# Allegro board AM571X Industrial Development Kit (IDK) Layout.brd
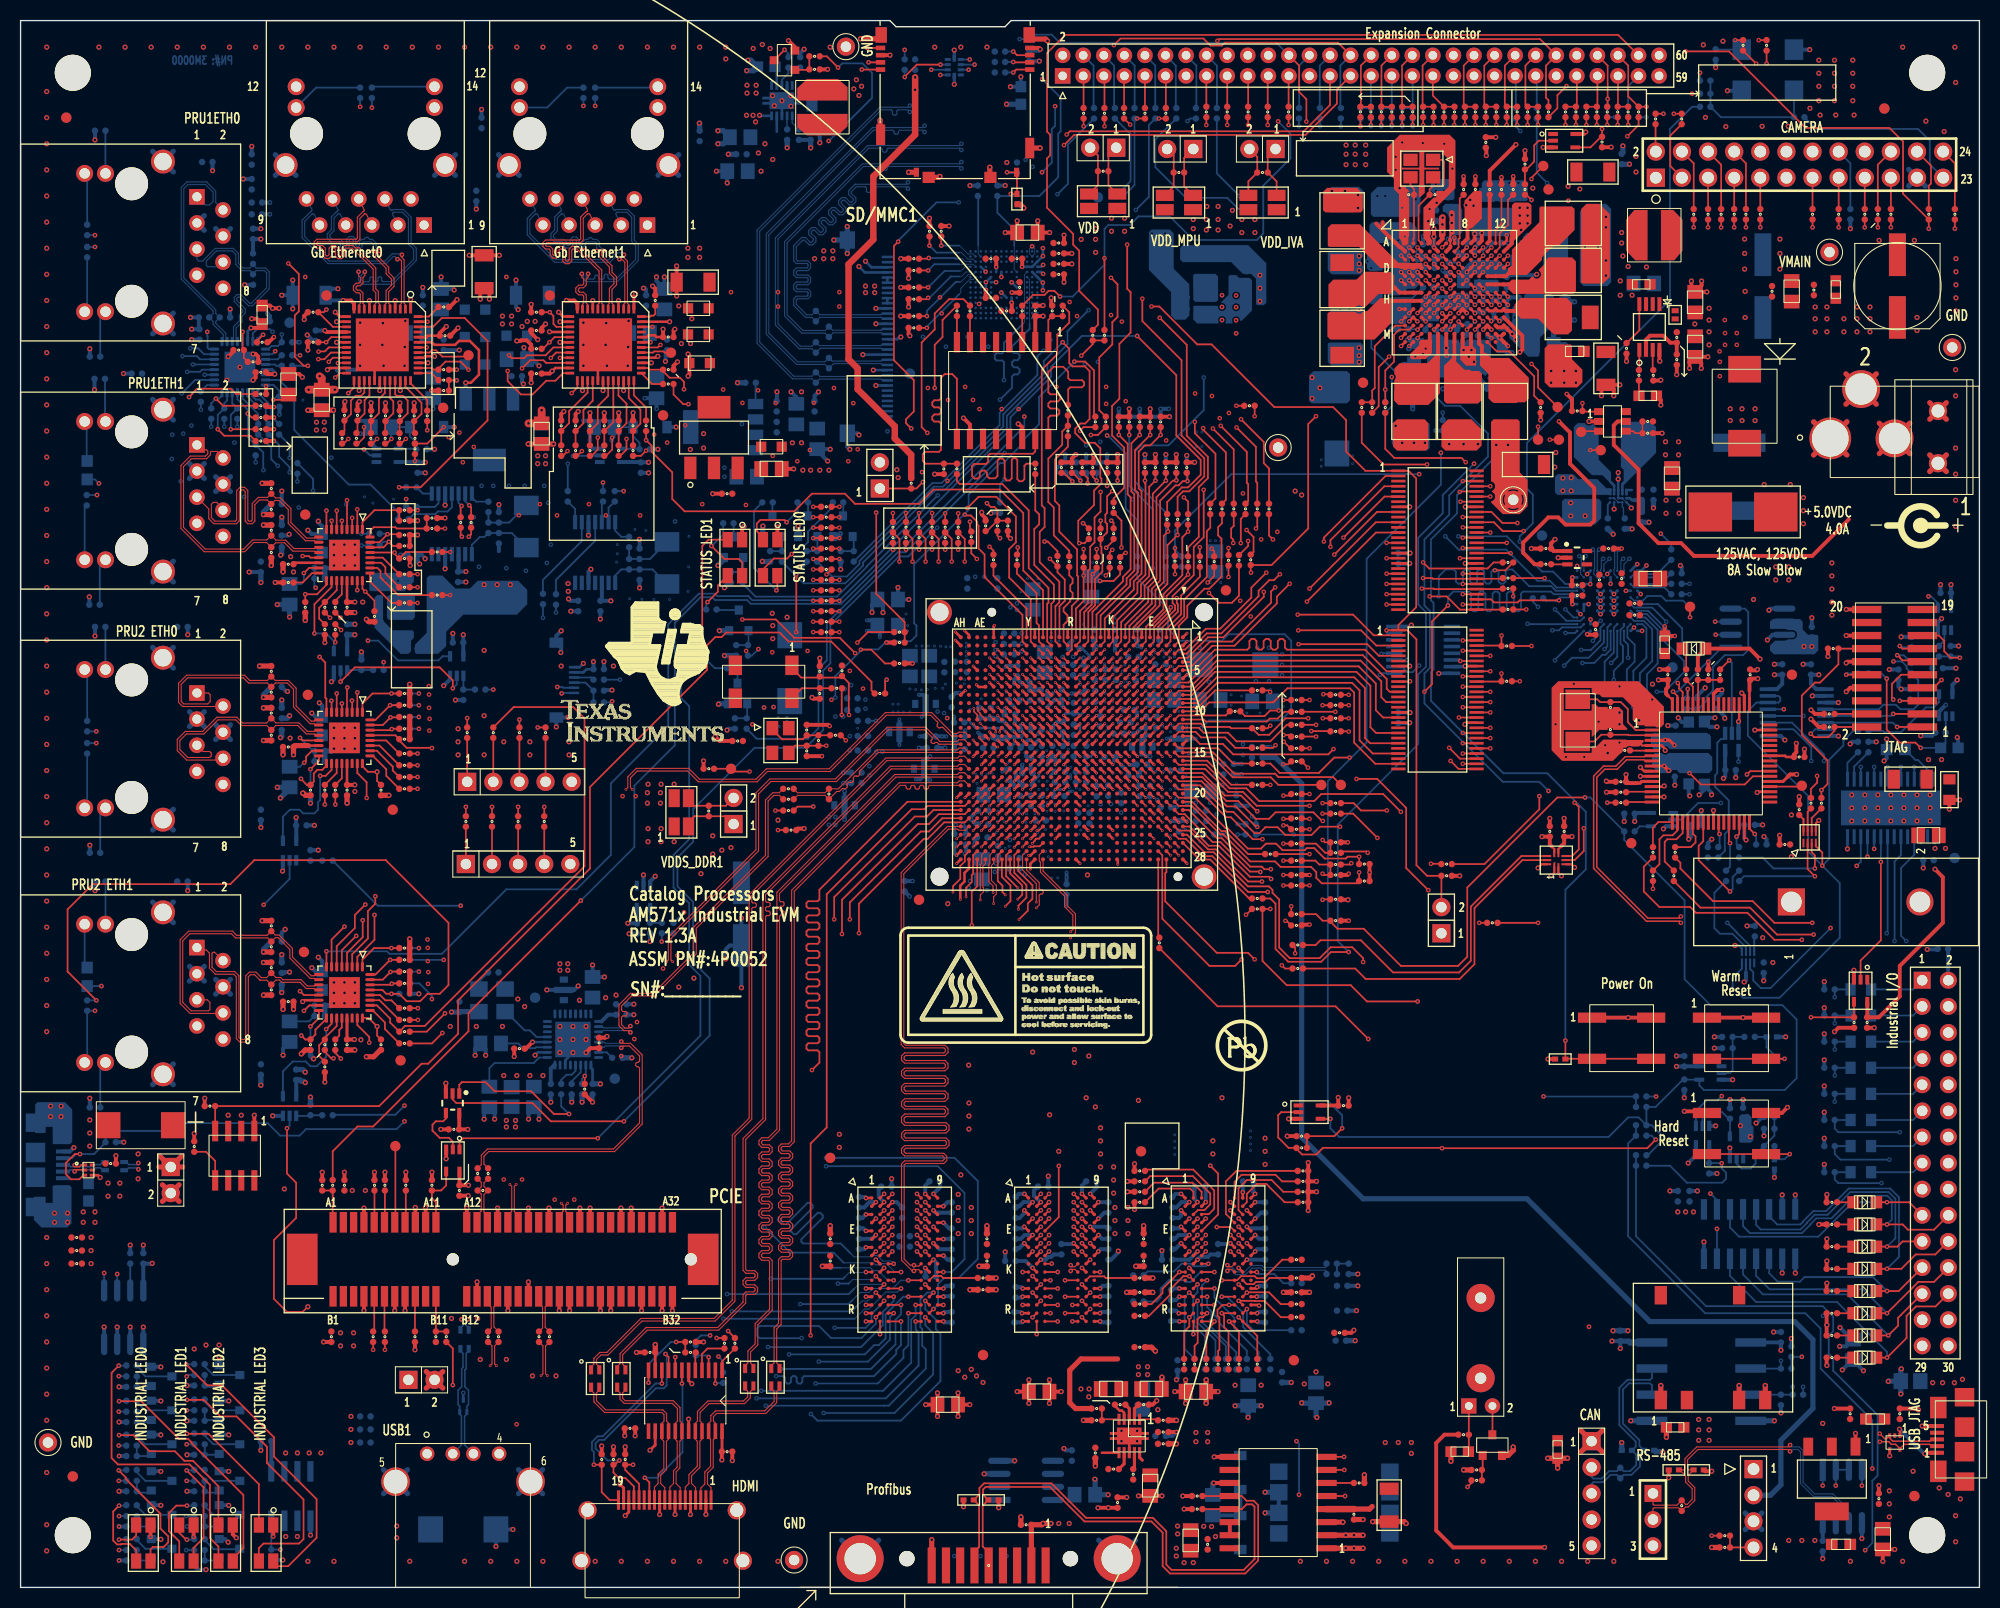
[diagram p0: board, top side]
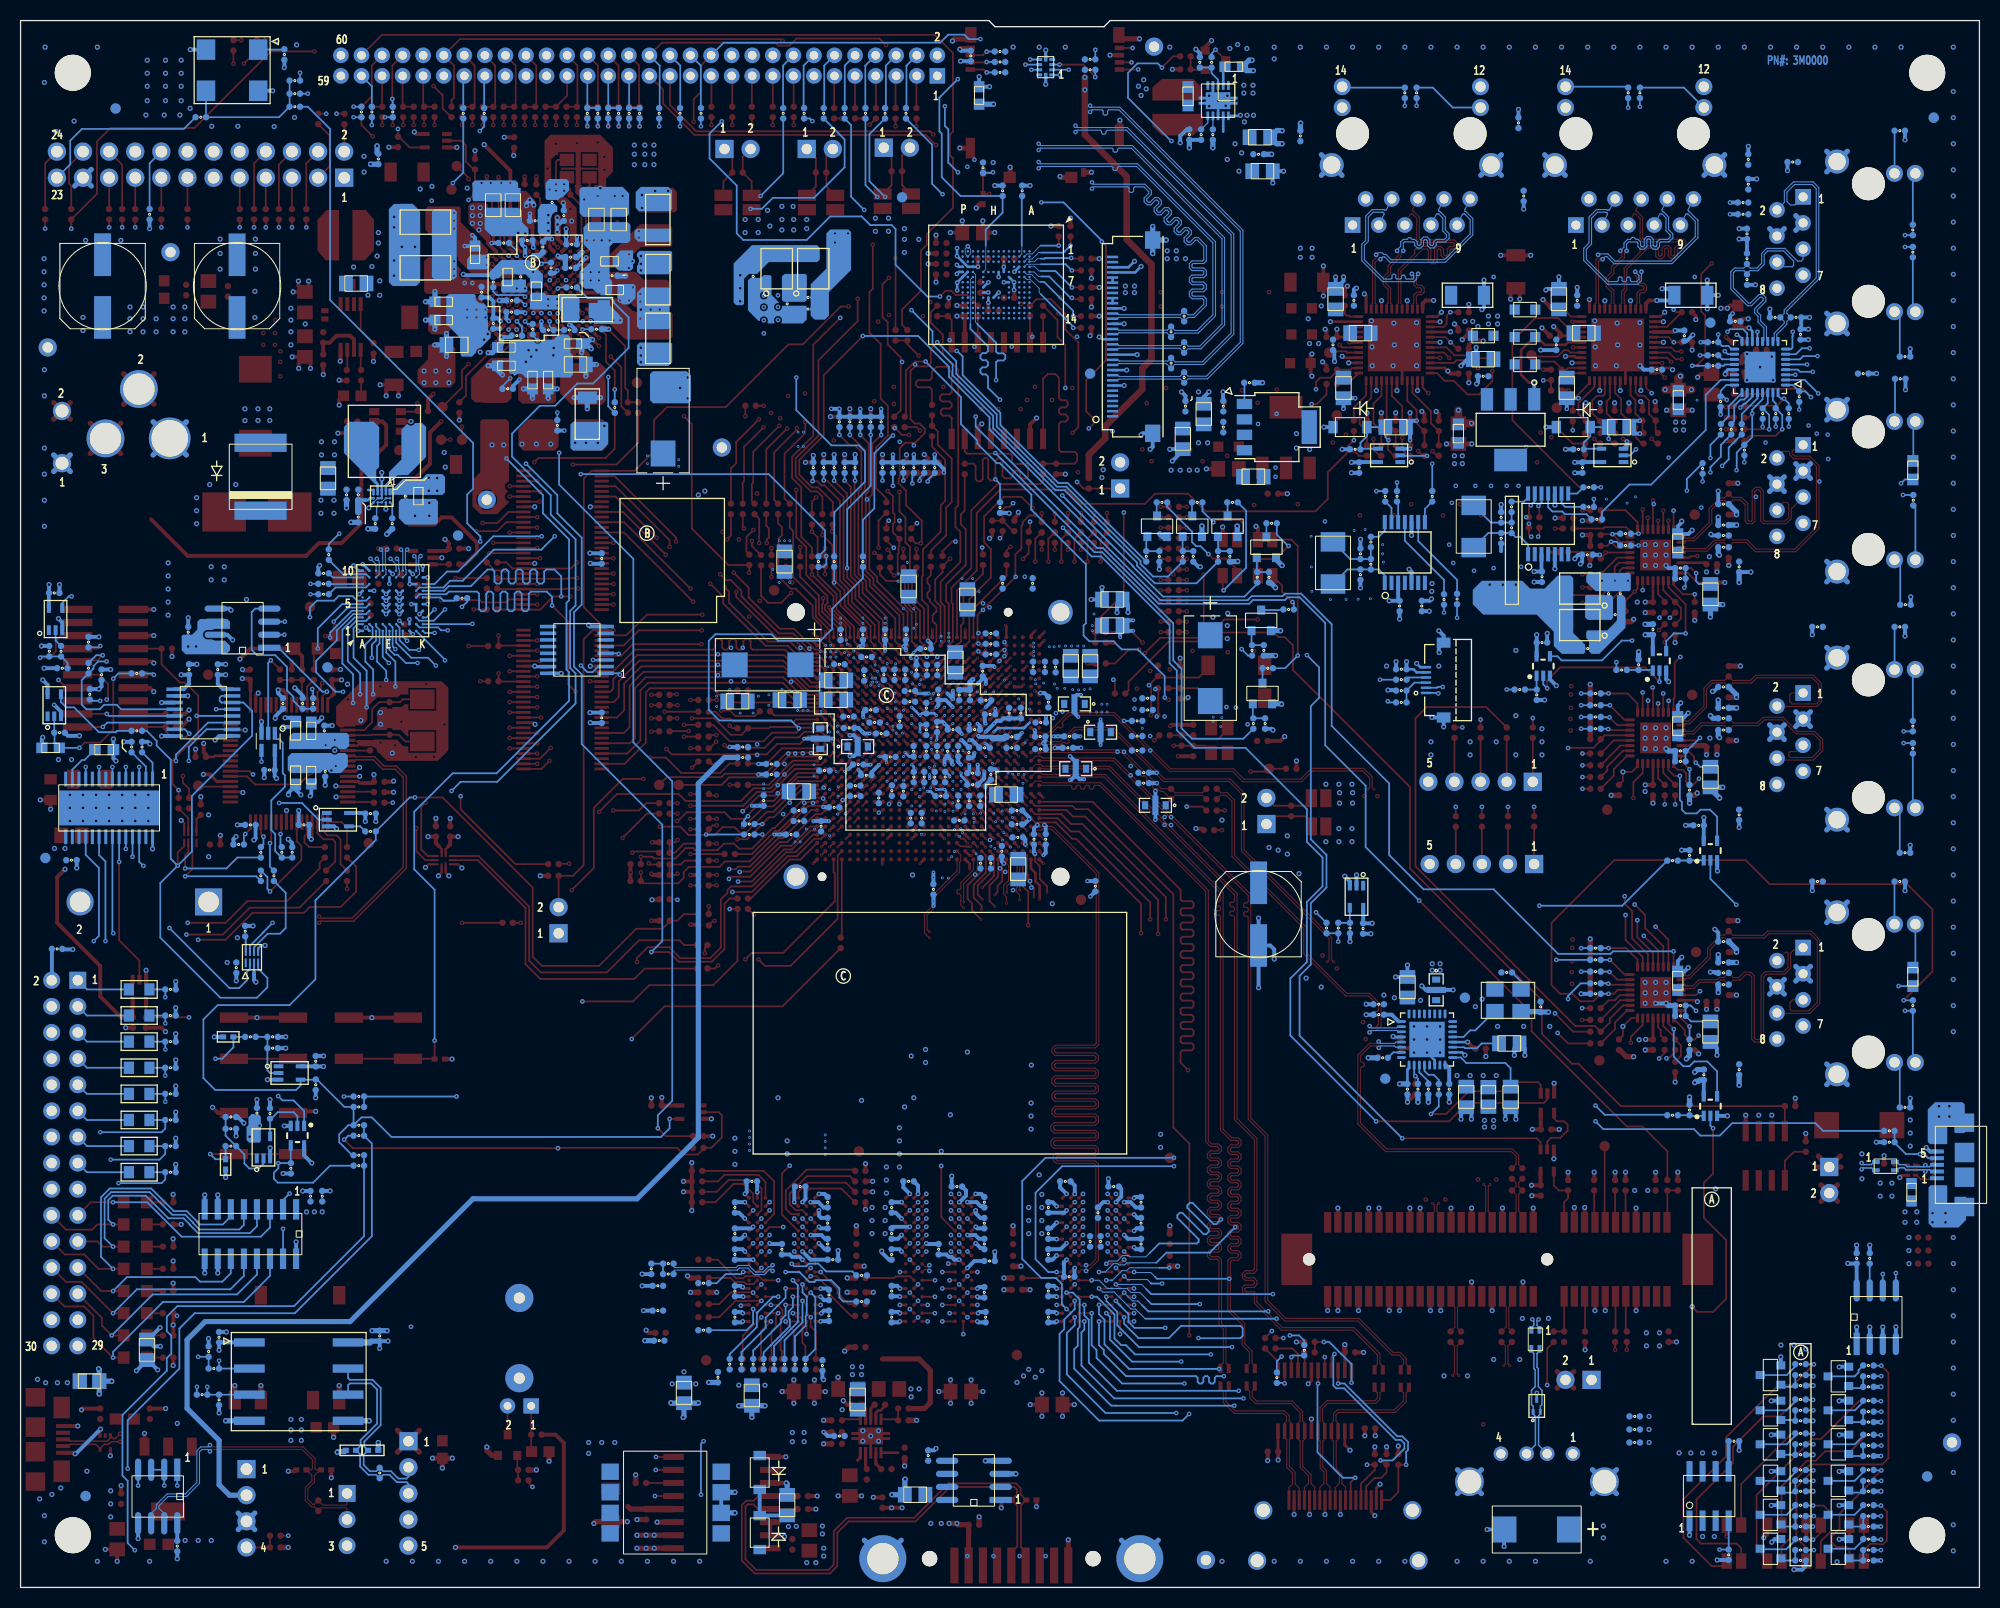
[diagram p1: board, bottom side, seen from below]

Outline 190.5 x 152.4 mm; copper layers: TOP, L2_GND1, L3_SIG1, L4_SIG2, L5_GND2, L6_PWR1, L7_PWR2, L8_GND3, L9_SIG3, L10_SIG4, L11_GND4, BOTTOM. Coordinates in mm from the lower left corner of the outline.
Outline path: 0,152.4 0,0 190.5,0 190.5,152.4 96.34,152.4 95.74,151.8 85.14,151.8 84.54,152.4 0,152.4

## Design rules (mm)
net group AM57XX_HDMI_CLK+: nets AM57XX_HDMI_CLK+ HDMI_CLK+
net group AM57XX_HDMI_CLK-: nets AM57XX_HDMI_CLK- HDMI_CLK-
net group AM57XX_HDMI_TX0+: nets AM57XX_HDMI_TX0+ HDMI_TX0+
net group AM57XX_HDMI_TX0-: nets AM57XX_HDMI_TX0- HDMI_TX0-
net group AM57XX_HDMI_TX1+: nets AM57XX_HDMI_TX1+ HDMI_TX1+
net group AM57XX_HDMI_TX1-: nets AM57XX_HDMI_TX1- HDMI_TX1-
net group AM57XX_HDMI_TX2+: nets AM57XX_HDMI_TX2+ HDMI_TX2+
net group AM57XX_HDMI_TX2-: nets AM57XX_HDMI_TX2- HDMI_TX2-
net group AM57XX_PCIE_PETN0: nets AM57XX_PCIE_PETN0 PCIECONN_PETN0
net group AM57XX_PCIE_PETN1: nets AM57XX_PCIE_PETN1 PCIECONN_PETN1
net group AM57XX_PCIE_PETP0: nets AM57XX_PCIE_PETP0 PCIECONN_PETP0
net group AM57XX_PCIE_PETP1: nets AM57XX_PCIE_PETP1 PCIECONN_PETP1
net group AM57XX_PCIE_REF_CLKN: nets AM57XX_PCIE_REF_CLKN SERDES_REF_CLKN
net group AM57XX_PCIE_REF_CLKP: nets AM57XX_PCIE_REF_CLKP SERDES_REF_CLKP
net group AM57XX_PRU1ETH1_TXCLK: nets AM57XX_PRU1ETH1_TXCLK PRU1ETH1_TXCLK
net group AM57XX_PRU1ETH1_TXD2: nets AM57XX_PRU1ETH1_TXD2 PRU1ETH1_TXD2
net group AM57XX_PRU1ETH1_TXD3: nets AM57XX_PRU1ETH1_TXD3 PRU1ETH1_TXD3
net group AM57XX_PRU1ETH1_TXEN: nets AM57XX_PRU1ETH1_TXEN PRU1ETH1_TXEN
net group AM57XX_PRU2ETH0_CRS: nets AM57XX_PRU2ETH0_CRS PRU2ETH0_CRS
net group AM57XX_PRU2ETH0_MRCLK: nets AM57XX_PRU2ETH0_MRCLK PRU2ETH0_RXCLK
net group AM57XX_PRU2ETH0_RXD0: nets AM57XX_PRU2ETH0_RXD0 PRU2ETH0_RXD0
net group AM57XX_PRU2ETH0_RXD1: nets AM57XX_PRU2ETH0_RXD1 PRU2ETH0_RXD1
net group AM57XX_PRU2ETH0_RXD2: nets AM57XX_PRU2ETH0_RXD2 PRU2ETH0_RXD2
net group AM57XX_PRU2ETH0_RXD3: nets AM57XX_PRU2ETH0_RXD3 PRU2ETH0_RXD3
net group AM57XX_PRU2ETH0_RXDV: nets AM57XX_PRU2ETH0_RXDV PRU2ETH0_RXDV
net group AM57XX_PRU2ETH0_RXER: nets AM57XX_PRU2ETH0_RXER PRU2ETH0_RXERR
net group AM57XX_PRU2ETH0_TXCLK: nets AM57XX_PRU2ETH0_TXCLK PRU2ETH0_TXCLK
net group AM57XX_PRU2ETH0_TXD0: nets AM57XX_PRU2ETH0_TXD0 PRU2ETH0_TXD0
net group AM57XX_PRU2ETH0_TXD1: nets AM57XX_PRU2ETH0_TXD1 PRU2ETH0_TXD1
net group AM57XX_PRU2ETH0_TXD2: nets AM57XX_PRU2ETH0_TXD2 PRU2ETH0_TXD2
net group AM57XX_PRU2ETH0_TXD3: nets AM57XX_PRU2ETH0_TXD3 PRU2ETH0_TXD3
net group AM57XX_PRU2ETH0_TXEN: nets AM57XX_PRU2ETH0_TXEN PRU2ETH0_TXEN
net group AM57XX_PRU2ETH1_COL: nets AM57XX_PRU2ETH1_COL PRU2ETH1_COL
net group AM57XX_PRU2ETH1_CRS: nets AM57XX_PRU2ETH1_CRS PRU2ETH1_CRS
net group AM57XX_PRU2ETH1_MRCLK: nets AM57XX_PRU2ETH1_MRCLK PRU2ETH1_RXCLK
net group AM57XX_PRU2ETH1_RXD0: nets AM57XX_PRU2ETH1_RXD0 PRU2ETH1_RXD0
net group AM57XX_PRU2ETH1_RXD1: nets AM57XX_PRU2ETH1_RXD1 PRU2ETH1_RXD1
net group AM57XX_PRU2ETH1_RXD2: nets AM57XX_PRU2ETH1_RXD2 PRU2ETH1_RXD2
net group AM57XX_PRU2ETH1_RXD3: nets AM57XX_PRU2ETH1_RXD3 PRU2ETH1_RXD3
net group AM57XX_PRU2ETH1_RXDV: nets AM57XX_PRU2ETH1_RXDV PRU2ETH1_RXDV
net group AM57XX_PRU2ETH1_RXER: nets AM57XX_PRU2ETH1_RXER PRU2ETH1_RXERR
net group AM57XX_PRU2ETH1_TXCLK: nets AM57XX_PRU2ETH1_TXCLK PRU2ETH1_TXCLK
net group AM57XX_PRU2ETH1_TXD0: nets AM57XX_PRU2ETH1_TXD0 PRU2ETH1_TXD0
net group AM57XX_PRU2ETH1_TXD1: nets AM57XX_PRU2ETH1_TXD1 PRU2ETH1_TXD1
net group AM57XX_PRU2ETH1_TXD2: nets AM57XX_PRU2ETH1_TXD2 PRU2ETH1_TXD2
net group AM57XX_PRU2ETH1_TXD3: nets AM57XX_PRU2ETH1_TXD3 PRU2ETH1_TXD3
net group AM57XX_PRU2ETH1_TXEN: nets AM57XX_PRU2ETH1_TXEN PRU2ETH1_TXEN
net group AM57XX_RGMII1_RD0: nets AM57XX_RGMII1_RD0 ETH1_RXD0
net group AM57XX_RGMII1_RD1: nets AM57XX_RGMII1_RD1 ETH1_RXD1
net group AM57XX_RGMII1_RD2: nets AM57XX_RGMII1_RD2 ETH1_RXD2
net group AM57XX_RGMII1_RD3: nets AM57XX_RGMII1_RD3 ETH1_RXD3
net group AM57XX_RGMII1_RXCLK: nets AM57XX_RGMII1_RXCLK ETH1_RXCLK
net group AM57XX_RGMII1_RXCTL: nets AM57XX_RGMII1_RXCTL ETH1_RXDV
net group AM57XX_RGMII1_TD0: nets AM57XX_RGMII1_TD0 ETH1_TXD0
net group AM57XX_RGMII1_TD1: nets AM57XX_RGMII1_TD1 ETH1_TXD1
net group AM57XX_RGMII1_TD2: nets AM57XX_RGMII1_TD2 ETH1_TXD2
net group AM57XX_RGMII1_TD3: nets AM57XX_RGMII1_TD3 ETH1_TXD3
net group AM57XX_RGMII1_TXCLK: nets AM57XX_RGMII1_TXCLK ETH1_TXCLK
net group AM57XX_RGMII1_TXCTL: nets AM57XX_RGMII1_TXCTL ETH1_TXEN
net group AM57XX_RTCK: nets AM57XX_RTCK RTCK
net group AM57XX_VIN1B_DATA0: nets AM57XX_VIN1B_DATA0 CAM1_DATA0
net group AM57XX_VIN1B_DATA1: nets AM57XX_VIN1B_DATA1 CAM1_DATA1
net group AM57XX_VIN1B_DATA2: nets AM57XX_VIN1B_DATA2 CAM1_DATA2
net group AM57XX_VIN1B_DATA3: nets AM57XX_VIN1B_DATA3 CAM1_DATA3
net group AM57XX_VIN1B_DATA4: nets AM57XX_VIN1B_DATA4 CAM1_DATA4
net group AM57XX_VIN1B_DATA5: nets AM57XX_VIN1B_DATA5 CAM1_DATA5
net group AM57XX_VIN1B_DATA6: nets AM57XX_VIN1B_DATA6 CAM1_DATA6
net group AM57XX_VIN1B_DATA7: nets AM57XX_VIN1B_DATA7 CAM1_DATA7
net group AM57XX_VIN1B_HSYNC: nets AM57XX_VIN1B_HSYNC CAM1_HSYNC
net group AM57XX_VIN1B_PCLK: nets AM57XX_VIN1B_PCLK CAM1_PCLK
net group AM57XX_VIN1B_VSYNC: nets AM57XX_VIN1B_VSYNC CAM1_VSYNC
net group AM571X_RGMII0_RD0: nets AM571X_RGMII0_RD0 ETH0_RXD0
net group AM571X_RGMII0_RD1: nets AM571X_RGMII0_RD1 ETH0_RXD1
net group AM571X_RGMII0_RD2: nets AM571X_RGMII0_RD2 ETH0_RXD2
net group AM571X_RGMII0_RD3: nets AM571X_RGMII0_RD3 ETH0_RXD3
net group AM571X_RGMII0_RXCLK: nets AM571X_RGMII0_RXCLK ETH0_RXCLK
net group AM571X_RGMII0_RXCTL: nets AM571X_RGMII0_RXCTL ETH0_RXDV
net group AM571X_RGMII0_TD0: nets AM571X_RGMII0_TD0 ETH0_TXD0
net group AM571X_RGMII0_TD1: nets AM571X_RGMII0_TD1 ETH0_TXD1
net group AM571X_RGMII0_TD2: nets AM571X_RGMII0_TD2 ETH0_TXD2
net group AM571X_RGMII0_TD3: nets AM571X_RGMII0_TD3 ETH0_TXD3
net group AM571X_RGMII0_TXCLK: nets AM571X_RGMII0_TXCLK ETH0_TXCLK
net group AM571X_RGMII0_TXCTL: nets AM571X_RGMII0_TXCTL ETH0_TXEN
net group AM572X_QSPI_D1: nets AM572X_QSPI_D1 SPIMEM_D1
net group AM572X_USB2_D: nets AM572X_USB2_DM AM572X_USB2_DP
net group JTAG_TCK: nets JTAG_TCK TCK
net group PCIE: nets AM57XX_PCIE_PERN1 AM57XX_PCIE_PERP1
net group PCIE_REFCLKN: nets PCI_CONN_REFN PCIE_REFCLKN
net group PCIE_REFCLKP: nets PCI_CONN_REFP PCIE_REFCLKP
net group PR1_MII1_MR1_CLK: nets PR1_MII1_MR1_CLK PRU1ETH1_RXCLK
net group PR1_MII1_RXD0: nets PR1_MII1_RXD0 PRU1ETH1_RXD0
net group PR1_MII1_RXD1: nets PR1_MII1_RXD1 PRU1ETH1_RXD1
net group PR1_MII1_RXD2: nets PR1_MII1_RXD2 PRU1ETH1_RXD2
net group PR1_MII1_RXD3: nets PR1_MII1_RXD3 PRU1ETH1_RXD3
net group PR1_MII1_RXDV: nets PR1_MII1_RXDV PRU1ETH1_RXDV
net group PR1_MII1_RXER: nets PR1_MII1_RXER PRU1ETH1_RXERR
net group PRU1ETH1_TXD0: nets AM571X_PRU1ETH1_TXD0 PRU1ETH1_TXD0
net group PRU1ETH1_TXD1: nets AM571X_PRU1ETH1_TXD1 PRU1ETH1_TXD1
net group SPIMEM_CSN: nets AM572X_QSPI_CSN SPIMEM_CSN
net group SPIMEM_D0: nets AM572X_QSPI_D0 SPIMEM_D0
net group SPIMEM_D2: nets AM572X_QSPI_D2 SPIMEM_D2
net group SPIMEM_D3: nets AM572X_QSPI_D3 SPIMEM_D3
net group USB2_CONN_D: nets USB2_CONN_DM USB2_CONN_DP
net group AM57XX_MMC1_CLK: nets MMC_CLK
net group AM57XX_MMC1_CMD: nets MMC_CMD
net group AM57XX_MMC1_DAT0: nets MMC_D0
net group AM57XX_MMC1_DAT1: nets MMC_D1
net group AM57XX_MMC1_DAT2: nets MMC_D2
net group AM57XX_MMC1_DAT3: nets MMC_D3
net group AM57XX_PRU1ETH_MDCLK: nets AM57XX_PRU1ETH_MDCLK PRU1ETH0_MDC PRU1ETH1_MDC
net group AM57XX_PRU1ETH_MDDATA: nets AM57XX_PRU1ETH_MDDATA PRU1ETH0_MDIO PRU1ETH1_MDIO
net group AM57XX_PRU2ETH_MDCLK: nets AM57XX_PRU2ETH_MDCLK PRU2ETH0_MDC PRU2ETH1_MDC
net group AM57XX_PRU2ETH_MDDATA: nets AM57XX_PRU2ETH_MDDATA PRU2ETH0_MDIO PRU2ETH1_MDIO
net group CLK: nets AM57XX_CLKOUT3 AM57XX_OSC0_IN AM57XX_OSC0_OUT ETH0GB_25MHZCLK ETH1GB_25MHZCLK INDUS_INPUTCLK N17745755 OSC0_OUT PRU1ETH0_25MHZCLK PRU1ETH1_25MHZCLK PRU2ETH0_25MHZCLK PRU2ETH1_25MHZCLK SRCCLK XTIN XTOUT
net group DDR_ADD: nets DDR_CKE
net group PRU1ETH0: nets PR1_MII0_RXD0 PR1_MII0_RXD1 PR1_MII0_RXD2 PR1_MII0_RXD3 PR1_MII0_RXDV PR1_MII0_RXER PR1_MII0_TXD0 PR1_MII0_TXD1 PR1_MII0_TXD2 PR1_MII0_TXD3 PR1_MII0_TXEN PR1_MII_MR0_CLK PR1_MII_MT0_CLK PRU1ETH0_RXCLK PRU1ETH0_RXD0 PRU1ETH0_RXD1 PRU1ETH0_RXD2 PRU1ETH0_RXD3 PRU1ETH0_RXDV PRU1ETH0_RXERR PRU1ETH0_TXCLK PRU1ETH0_TXD0
net group PRU1ETH0_TXD1: nets PRU1ETH0_TXD1
net group PRU1ETH0_TXD2: nets PRU1ETH0_TXD2
net group PRU1ETH0_TXD3: nets PRU1ETH0_TXD3
net group PRU1ETH0_TXEN: nets PRU1ETH0_TXEN
net group PRU2ETHER0_D: nets PRU2ETHER0_RDN PRU2ETHER0_RDP PRU2ETHER0_TDN PRU2ETHER0_TDP
net group PWR: nets ETH0_LDO_O N11219802 N11219922 N18915671 N18915723 N19923825 N19923832 N19923851 N19923852 N20128389 N20287248 N20287584 N20664562 N20665027 N21605448 N22829911 USB1_OVRCURN V1_8PHY_PCIE V5_0DFB VANA_OUT VLDO1_OUT VPP_CONN
net group SD_MMC_CC: nets AM57XX_MMC1_CLK AM57XX_MMC1_CMD AM57XX_MMC1_DAT0 AM57XX_MMC1_DAT1 AM57XX_MMC1_DAT2 AM57XX_MMC1_DAT3
net group SPIMEM_CLK: nets AM572X_QSPI_CLK AM572X_QSPI_RTCLK QSPI_CLK SPIMEM_CLK
net group VOUT: nets AM57XX_VOUT1_D0 AM57XX_VOUT1_D1 AM57XX_VOUT1_D2 AM57XX_VOUT1_D3 AM57XX_VOUT1_D4 AM57XX_VOUT1_D5 AM57XX_VOUT1_D6 AM57XX_VOUT1_D7 AM57XX_VOUT1_D8 AM57XX_VOUT1_D9 AM57XX_VOUT1_D10 AM57XX_VOUT1_D11 AM57XX_VOUT1_D12 AM57XX_VOUT1_D13 AM57XX_VOUT1_D14 AM57XX_VOUT1_D15 AM57XX_VOUT1_D16 AM57XX_VOUT1_D17 AM57XX_VOUT1_D18 AM57XX_VOUT1_D19 AM57XX_VOUT1_D20 AM57XX_VOUT1_D21 AM57XX_VOUT1_D22 AM57XX_VOUT1_D23 AM57XX_VOUT1_VSYNC
nets with their own width: min track width 0.381; nets VSDMMC

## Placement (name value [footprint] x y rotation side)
C1  24pF  [SM-7351-CAP-0402]  76.45 83.39 90 top
C2  24pF  [SM-7351-CAP-0402]  76.45 81.36 270 top
C3  0.01uF  [SM-7351-CAP-0402]  167.51 46.14 90 bottom
C4  1uF  [SM-7351-CAP-0402]  170.05 44.61 180 bottom
C5  1uF  [SM-7351-CAP-0402]  165.99 53.55 180 bottom
C6  10uF  [SM-7351-CAP-0805]  93.49 69.87 270 bottom
C7  0.01uF  [SM-7351-CAP-0402]  93.52 72.95 180 bottom
C8  0.01uF  [SM-7351-CAP-0402]  93.6 74.22 180 bottom
C9  0.01uF  [SM-7351-CAP-0402]  95.07 71.61 270 bottom
C10  0.01uF  [SM-7351-CAP-0402]  97.16 70.44 270 bottom
C11  0.01uF  [SM-7351-CAP-0402]  93.6 75.57 180 bottom
C12  0.01uF  [SM-7351-CAP-0402]  90.8 72.77 90 bottom
C20  0.1uF  [SM-7351-CAP-0402]  170.33 126.07 90 top
C21  0.1uF  [SM-7351-CAP-0402]  174.4 126.19 90 top
C22  10uF  [SM-7351-CAP-0805]  172.24 126.07 90 top
C23  1uF  [SM-7351-CAP-0603]  176.53 126.24 90 top
C24  100uF  [SM-7351-CAP-SMDCAN]  169.44 126.57 270 bottom
C25  27pF  [SM-7351-CAP-0402]  135 135.46 0 top
C26  27pF  [SM-7351-CAP-0402]  137.54 135.46 180 top
C27  0.1uF  [SM-7351-CAP-0402]  140.34 135.97 270 top
C28  0.01uF  [SM-7351-CAP-0402]  98.68 124.16 90 top
C29  0.01uF  [SM-7351-CAP-0402]  81.53 35.43 270 bottom
C30  0.01uF  [SM-7351-CAP-0402]  84.2 38.99 0 bottom
C31  0.01uF  [SM-7351-CAP-0402]  81.53 37.46 270 bottom
C32  0.01uF  [SM-7351-CAP-0402]  90.55 36.96 90 bottom
C33  22uF  [SM-7351-CAP-0805]  90.17 17.78 0 top
C34  0.01uF  [SM-7351-CAP-0402]  88.9 39.5 0 bottom
C35  0.01uF  [SM-7351-CAP-0402]  90.55 26.29 270 bottom
C36  0.01uF  [SM-7351-CAP-0402]  90.55 32.38 90 bottom
C37  0.01uF  [SM-7351-CAP-0402]  90.55 28.83 90 bottom
C38  0.01uF  [SM-7351-CAP-0402]  90.55 34.42 270 bottom
C39  0.01uF  [SM-7351-CAP-0402]  88.52 30.23 0 bottom
C40  0.01uF  [SM-7351-CAP-0402]  85.47 33.66 90 bottom
C41  0.01uF  [SM-7351-CAP-0402]  85.72 36.45 90 bottom
C42  0.01uF  [SM-7351-CAP-0402]  81.53 33.4 270 bottom
C43  0.01uF  [SM-7351-CAP-0402]  86.49 33.66 90 bottom
C44  0.1uF  [SM-7351-CAP-0402]  78.74 33.91 270 top
C45  0.1uF  [SM-7351-CAP-0402]  78.74 31.75 270 top
C46  0.1uF  [SM-7351-CAP-0402]  93.6 28.96 0 top
C47  0.1uF  [SM-7351-CAP-0402]  109.22 33.91 270 top
C48  0.01uF  [SM-7351-CAP-0402]  105.79 36.96 90 bottom
C49  0.01uF  [SM-7351-CAP-0402]  96.77 37.46 270 bottom
C50  0.01uF  [SM-7351-CAP-0402]  104.14 39.5 0 bottom
C51  0.01uF  [SM-7351-CAP-0402]  96.65 26.29 270 bottom
C52  22uF  [SM-7351-CAP-0805]  99.06 19.05 0 top
C53  0.1uF  [SM-7351-CAP-0402]  109.22 31.75 270 top
C54  0.1uF  [SM-7351-CAP-0402]  124.08 28.7 0 top
C55  0.01uF  [SM-7351-CAP-0402]  105.79 26.29 270 bottom
C56  0.01uF  [SM-7351-CAP-0402]  96.27 31.75 180 bottom
C57  0.01uF  [SM-7351-CAP-0402]  96.77 28.7 90 bottom
C58  0.01uF  [SM-7351-CAP-0402]  101.22 32.89 270 bottom
C59  0.01uF  [SM-7351-CAP-0402]  96.77 33.4 270 bottom
C60  0.01uF  [SM-7351-CAP-0402]  111.51 31.88 180 bottom
C61  0.01uF  [SM-7351-CAP-0402]  121.03 32.38 270 bottom
C62  0.01uF  [SM-7351-CAP-0402]  116.46 32.89 270 bottom
C63  0.01uF  [SM-7351-CAP-0402]  119.38 39.5 0 bottom
C64  22uF  [SM-7351-CAP-0805]  114.3 19.05 0 top
C65  0.01uF  [SM-7351-CAP-0402]  105.79 32.38 270 bottom
C66  0.01uF  [SM-7351-CAP-0402]  105.79 28.83 90 bottom
C67  0.01uF  [SM-7351-CAP-0402]  96.77 35.43 270 bottom
C68  0.01uF  [SM-7351-CAP-0402]  105.79 34.42 270 bottom
C69  0.01uF  [SM-7351-CAP-0402]  99.44 38.99 0 bottom
C70  0.01uF  [SM-7351-CAP-0402]  121.03 26.29 270 bottom
C71  0.01uF  [SM-7351-CAP-0402]  114.68 38.99 0 bottom
C72  0.01uF  [SM-7351-CAP-0402]  111.89 26.42 270 bottom
C73  0.01uF  [SM-7351-CAP-0402]  121.03 34.42 270 bottom
C74  0.01uF  [SM-7351-CAP-0402]  112.01 37.46 270 bottom
C75  0.01uF  [SM-7351-CAP-0402]  121.03 28.83 90 bottom
C76  0.01uF  [SM-7351-CAP-0402]  121.03 36.96 90 bottom
C77  0.01uF  [SM-7351-CAP-0402]  112.01 35.43 270 bottom
C78  0.01uF  [SM-7351-CAP-0402]  112.01 33.4 270 bottom
C79  0.01uF  [SM-7351-CAP-0402]  111.89 28.45 90 bottom
C80  0.1uF  [SM-7351-CAP-0402]  93.98 33.91 270 top
C81  0.01uF  [SM-7351-CAP-0402]  96.14 79.08 90 bottom
C82  0.1uF  [SM-7351-CAP-0402]  93.98 31.75 270 top
C83  0.1uF  [SM-7351-CAP-0402]  108.84 28.7 0 top
C84  0.001uF  [SM-7351-CAP-0402]  110.87 14.73 180 bottom
C85  0.1uF  [SM-7351-CAP-0402]  129.16 30.99 270 bottom
C86  0.001uF  [SM-7351-CAP-0402]  111.12 16.26 0 top
C87  0.1uF  [SM-7351-CAP-0402]  128.52 29.34 0 bottom
C88  10uF  [SM-7351-CAP-0805]  109.86 9.91 270 top
C89  0.1uF  [SM-7351-CAP-0402]  128.27 24.77 0 top
C90  0.1uF  [SM-7351-CAP-0402]  109.22 17.78 0 top
C91  10uF  [SM-7351-CAP-0805]  109.98 19.3 0 top
C92  10uF  [SM-7351-CAP-0805]  109.09 18.29 270 bottom
C93  0.1uF  [SM-7351-CAP-0402]  108.84 23.37 0 top
C94  0.1uF  [SM-7351-CAP-0402]  112.52 21.59 270 bottom
C95  10uF  [SM-7351-CAP-0805]  125.98 18.92 270 bottom
C96  10uF  [SM-7351-CAP-0805]  119.38 18.67 270 bottom
C97  10uF  [SM-7351-CAP-0805]  106.05 19.3 180 top
C98  0.1uF  [SM-7351-CAP-0402]  128.4 24 0 bottom
C99  0.1uF  [SM-7351-CAP-0402]  104.52 13.08 270 top
C100  0.1uF  [SM-7351-CAP-0402]  106.93 17.78 180 top
C101  10pF  [SM-7351-CAP-0402]  104.65 16.26 180 top
C102  0.1uF  [SM-7351-CAP-0402]  22.99 134.7 0 bottom
C103  0.1uF  [SM-7351-CAP-0402]  22.99 133.56 0 bottom
C104  0.1uF  [SM-7351-CAP-0402]  17.4 121.87 270 bottom
C105  0.01uF  [SM-7351-CAP-0402]  23.37 118.19 180 top
C106  4700pF  [SM-7351-CAP-0402]  18.16 138.64 180 bottom
C107  0.1uF  [SM-7351-CAP-0402]  22.61 131.65 90 bottom
C108  0.1uF  [SM-7351-CAP-0402]  25.17 115.35 270 bottom
C109  0.1uF  [SM-7351-CAP-0402]  22.61 119.21 0 top
C110  10uF  [SM-7351-CAP-0805]  26.06 117.02 90 top
C111  0.1uF  [SM-7351-CAP-0402]  21.21 120.35 180 top
C112  0.01uF  [SM-7351-CAP-0402]  23.75 123.14 0 bottom
C113  0.01uF  [SM-7351-CAP-0402]  42.55 91.9 180 bottom
C114  0.01uF  [SM-7351-CAP-0402]  97.92 79.2 180 bottom
C115  0.01uF  [SM-7351-CAP-0402]  96.14 70.44 270 bottom
C116  0.1uF  [SM-7351-CAP-0402]  24.89 102.32 0 bottom
C117  0.1uF  [SM-7351-CAP-0402]  24.89 101.17 0 bottom
C118  0.01uF  [SM-7351-CAP-0402]  26.03 99.52 180 top
C119  0.1uF  [SM-7351-CAP-0402]  24.89 105.36 0 bottom
C120  0.01uF  [SM-7351-CAP-0402]  31.75 95.33 270 top
C121  4700pF  [SM-7351-CAP-0402]  11.3 118.06 0 bottom
C122  0.1uF  [SM-7351-CAP-0402]  24.89 103.33 0 bottom
C123  0.1uF  [SM-7351-CAP-0402]  34.42 94.44 270 top
C124  0.1uF  [SM-7351-CAP-0402]  29.08 99.14 0 bottom
C125  10uF  [SM-7351-CAP-0805]  26.16 96.6 270 bottom
C126  0.1uF  [SM-7351-CAP-0402]  29.08 98.13 0 bottom
C127  0.01uF  [SM-7351-CAP-0402]  31.75 93.17 90 bottom
C128  0.1uF  [SM-7351-CAP-0402]  24.89 84.54 0 bottom
C129  0.1uF  [SM-7351-CAP-0402]  24.89 83.39 0 bottom
C130  0.01uF  [SM-7351-CAP-0402]  31.75 77.55 270 top
C131  4700pF  [SM-7351-CAP-0402]  15.75 93.43 180 bottom
C132  0.1uF  [SM-7351-CAP-0402]  24.89 85.55 0 bottom
C133  0.1uF  [SM-7351-CAP-0402]  24.89 87.58 0 bottom
C134  0.1uF  [SM-7351-CAP-0402]  29.08 80.35 0 bottom
C135  0.1uF  [SM-7351-CAP-0402]  35.05 77.55 270 top
C136  10uF  [SM-7351-CAP-0805]  26.16 78.82 270 bottom
C137  0.01uF  [SM-7351-CAP-0402]  26.03 81.74 180 top
C138  0.1uF  [SM-7351-CAP-0402]  29.08 81.36 0 bottom
C139  0.01uF  [SM-7351-CAP-0402]  27.3 74.12 0 bottom
C140  0.1uF  [SM-7351-CAP-0402]  24.89 59.77 0 bottom
C141  0.1uF  [SM-7351-CAP-0402]  24.89 58.63 0 bottom
C142  0.01uF  [SM-7351-CAP-0402]  26.03 56.98 180 top
C143  0.1uF  [SM-7351-CAP-0402]  24.89 60.79 0 bottom
C144  0.01uF  [SM-7351-CAP-0402]  31.75 52.79 270 top
C145  0.1uF  [SM-7351-CAP-0402]  24.89 62.82 0 bottom
C146  4700pF  [SM-7351-CAP-0402]  15.75 68.66 180 bottom
C147  0.1uF  [SM-7351-CAP-0402]  35.05 52.79 270 top
C148  0.1uF  [SM-7351-CAP-0402]  29.08 56.6 0 bottom
C149  10uF  [SM-7351-CAP-0805]  26.16 54.06 270 bottom
C150  0.1uF  [SM-7351-CAP-0402]  29.08 55.58 0 bottom
C151  0.01uF  [SM-7351-CAP-0402]  26.8 49.87 90 bottom
C152  0.01uF  [SM-7351-CAP-0402]  155.7 138.94 90 bottom
C153  0.1uF  [SM-7351-CAP-0402]  48.26 117.81 0 bottom
C154  10uF  [SM-7351-CAP-0805]  48.26 119.46 0 bottom
C155  0.1uF  [SM-7351-CAP-0402]  28.7 121.75 270 bottom
C156  10uF  [SM-7351-CAP-0805]  29.29 115.5 270 top
C157  47uF  [SM-7351-CAP-1206]  28.07 125.68 0 bottom
C158  47uF  [SM-7351-CAP-1206]  45.09 127.97 270 top
C159  10uF  [SM-7351-CAP-0805]  40.13 116.67 270 bottom
C160  0.1uF  [SM-7351-CAP-0402]  31.37 118.45 0 bottom
C161  10uF  [SM-7351-CAP-0805]  40.89 125.3 90 bottom
C162  0.1uF  [SM-7351-CAP-0402]  39.12 125.18 90 bottom
C163  10uF  [SM-7351-CAP-0805]  38.48 122 180 bottom
C164  0.1uF  [SM-7351-CAP-0402]  41.15 120.86 270 bottom
C165  0.01uF  [SM-7351-CAP-0402]  41.27 121.75 0 top
C166  0.1uF  [SM-7351-CAP-0402]  22.48 138.89 270 bottom
C167  0.1uF  [SM-7351-CAP-0402]  44.32 135.34 90 bottom
C168  10uF  [SM-7351-CAP-0805]  35.05 112.86 180 bottom
C169  0.01uF  [SM-7351-CAP-0402]  42.55 98.3 270 bottom
C170  0.01uF  [SM-7351-CAP-0402]  38.13 100.44 180 bottom
C171  0.01uF  [SM-7351-CAP-0402]  38.61 108.92 270 bottom
C172  18pF  [SM-7351-CAP-0402]  46.51 102.05 90 bottom
C173  18pF  [SM-7351-CAP-0402]  46.51 104.08 270 bottom
C174  0.1uF  [SM-7351-CAP-0402]  50.16 122.26 180 top
C175  10uF  [SM-7351-CAP-0805]  50.67 112.22 270 top
C176  0.1uF  [SM-7351-CAP-0402]  68.71 106.38 180 top
C177  10uF  [SM-7351-CAP-0805]  73.02 108.79 0 top
C178  47uF  [SM-7351-CAP-1206]  49.78 125.68 0 bottom
C179  47uF  [SM-7351-CAP-1206]  65.41 126.95 0 top
C180  10uF  [SM-7351-CAP-0805]  61.85 116.67 270 bottom
C181  0.1uF  [SM-7351-CAP-0402]  50.16 118.06 180 top
C182  10uF  [SM-7351-CAP-0805]  62.61 125.3 90 bottom
C183  0.1uF  [SM-7351-CAP-0402]  60.83 125.18 90 bottom
C184  10uF  [SM-7351-CAP-0805]  60.2 122 180 bottom
C185  0.1uF  [SM-7351-CAP-0402]  62.86 120.86 270 bottom
C186  0.01uF  [SM-7351-CAP-0402]  62.99 121.62 0 top
C187  0.1uF  [SM-7351-CAP-0402]  44.83 142.45 270 bottom
C188  0.1uF  [SM-7351-CAP-0402]  66.04 141.18 270 bottom
C189  10uF  [SM-7351-CAP-0805]  56.77 112.86 180 bottom
C190  0.01uF  [SM-7351-CAP-0402]  56.39 95.46 270 bottom
C191  0.01uF  [SM-7351-CAP-0402]  54.23 95.46 270 bottom
C192  0.01uF  [SM-7351-CAP-0402]  60.32 108.92 270 bottom
C193  18pF  [SM-7351-CAP-0402]  60.2 98.51 90 bottom
C194  18pF  [SM-7351-CAP-0402]  60.2 100.54 270 bottom
C195  0.01uF  [SM-7351-CAP-0402]  179.58 54.95 270 top
C196  0.001uF  [SM-7351-CAP-0402]  186.94 62.1 180 bottom
C197  0.022uF  [SM-7351-CAP-0402]  175.92 58.17 180 bottom
C198  0.022uF  [SM-7351-CAP-0402]  175.92 55.63 180 bottom
C199  0.022uF  [SM-7351-CAP-0402]  175.92 53.09 180 bottom
C200  0.022uF  [SM-7351-CAP-0402]  175.92 50.55 180 bottom
C201  0.022uF  [SM-7351-CAP-0402]  175.92 48.01 180 bottom
C202  0.022uF  [SM-7351-CAP-0402]  175.92 45.47 180 bottom
C203  0.022uF  [SM-7351-CAP-0402]  175.92 42.93 180 bottom
C204  0.022uF  [SM-7351-CAP-0402]  175.92 40.39 180 bottom
C205  2.2uF  [SM-7351-CAP-0805]  185.55 73.15 180 top
C206  10uF  [SM-7351-CAP-1206]  183.77 78.61 0 top
C207  0.01uF  [SM-7351-CAP-0402]  185.55 70.74 180 bottom
C208  2.2uF  [SM-7351-CAP-0805]  178.21 23.11 90 bottom
C209  1uF  [SM-7351-CAP-0402]  161.16 38.05 90 bottom
C210  0.01uF  [SM-7351-CAP-0402]  162.31 38.05 90 bottom
C211  0.1uF  [SM-7351-CAP-0402]  98.08 148.96 270 bottom
C212  4.7uF  [SM-7351-CAP-0603]  97.28 145.12 270 bottom
C213  0.1uF  [SM-7351-CAP-0402]  164.21 40.77 270 bottom
C214  0.01uF  [SM-7351-CAP-0402]  161.8 51.18 90 bottom
C215  10uF  [SM-7351-CAP-0805]  69.72 137.75 180 bottom
C216  0.01uF  [SM-7351-CAP-0402]  70.1 139.4 180 bottom
C217  4.7uF  [SM-7351-CAP-0603]  72.52 147.91 180 bottom
C218  4.7uF  [SM-7351-CAP-0805]  69.98 141.05 180 bottom
C219  0.01uF  [SM-7351-CAP-0402]  56.22 89.31 0 bottom
C220  0.01uF  [SM-7351-CAP-0402]  11.94 32 90 bottom
C221  0.01uF  [SM-7351-CAP-0402]  182.63 88.77 90 bottom
C222  10uF  [SM-7351-CAP-0805]  77.47 111.71 270 bottom
C223  0.1uF  [SM-7351-CAP-0402]  187.71 91.06 90 bottom
C224  DNI  [SM-7351-CAP-0805]  181.1 4.7 270 top
C225  0.1uF  [SM-7351-CAP-0402]  182.75 16.89 90 top
C226  0.1uF  [SM-7351-CAP-0402]  177.93 16.89 90 top
C228  0.01uF  [SM-7351-CAP-0402]  166.29 79.51 180 bottom
C229  0.1uF  [SM-7351-CAP-0402]  168.15 74.17 0 bottom
C230  0.01uF  [SM-7351-CAP-0402]  156.46 75.27 0 bottom
C231  4.7uF  [SM-7351-CAP-0603]  162.23 83.32 270 bottom
C232  0.1uF  [SM-7351-CAP-0402]  168.2 88.78 90 top
C233  0.1uF  [SM-7351-CAP-0402]  172.97 80.77 0 top
C234  0.1uF  [SM-7351-CAP-0402]  160.96 83.32 270 bottom
C235  0.1uF  [SM-7351-CAP-0402]  160.2 88.78 90 top
C236  0.1uF  [SM-7351-CAP-0402]  164.97 85.98 270 bottom
C237  4.7uF  [SM-7351-CAP-0603]  162.23 79 90 bottom
C238  0.1uF  [SM-7351-CAP-0402]  155.63 78.36 180 top
C239  0.1uF  [SM-7351-CAP-0402]  162.94 74.17 0 bottom
C240  0.1uF  [SM-7351-CAP-0402]  160.87 79.38 90 bottom
C241  4.7uF  [SM-7351-CAP-0603]  159.89 91.69 90 top
C242  0.1uF  [SM-7351-CAP-0402]  180.72 8.64 270 top
C243  18pF  [SM-7351-CAP-0402]  154.61 85.6 270 top
C244  18pF  [SM-7351-CAP-0402]  154.61 83.44 90 top
C245  0.1uF  [SM-7351-CAP-0402]  174.2 92.92 90 bottom
C246  15pF  [SM-7351-CAP-0402]  77.72 89.11 90 top
C247  15pF  [SM-7351-CAP-0402]  77.72 86.95 270 top
C248  0.01uF  [SM-7351-CAP-0402]  59.94 64.09 270 bottom
C249  3.3uF  [SM-7351-CAP-0603]  160.91 15.58 180 top
C250  3.3uF  [SM-7351-CAP-0603]  149.48 13.42 270 top
C251  0.01uF  [SM-7351-CAP-0402]  171.2 24.34 90 bottom
C252  0.1uF  [SM-7351-CAP-0402]  155.58 24.47 90 bottom
C253  100pF25V10%  [SM-7351-CAP-0402]  172.21 22.94 90 bottom
C254  100pF25V10%  [SM-7351-CAP-0402]  171.2 18.24 270 bottom
C255  0.01uF  [SM-7351-CAP-0402]  94.36 125.43 0 top
C256  0.01uF  [SM-7351-CAP-0402]  95.89 124.16 180 top
C257  0.01uF  [SM-7351-CAP-0402]  94.36 129.24 180 top
C258  0.01uF  [SM-7351-CAP-0402]  97.16 126.45 90 top
C261  0.01uF  [SM-7351-CAP-0402]  100.97 128.73 0 top
C262  0.01uF  [SM-7351-CAP-0402]  100.97 129.75 0 top
C263  0.01uF  [SM-7351-CAP-0402]  100.97 130.76 0 top
C264  0.01uF  [SM-7351-CAP-0402]  100.97 127.72 0 top
C265  1uF  [SM-7351-CAP-0402]  93.09 135.84 90 bottom
C266  10uF  [SM-7351-CAP-0805]  88.37 89.62 90 bottom
C267  0.1uF  [SM-7351-CAP-0402]  99.21 86.8 90 bottom
C268  47uF, 10V  [SM-7351-CAP-1206]  135.38 114.13 270 bottom
C269  47uF, 10V  [SM-7351-CAP-1206]  128.52 133.05 90 bottom
C270  47uF, 10V  [SM-7351-CAP-1206]  146.56 109.22 180 top
C271  47uF, 10V  [SM-7351-CAP-1206]  135.38 124.29 0 bottom
C272  4.7uF  [SM-7351-CAP-0603]  136.78 120.99 180 bottom
C273  4.7uF  [SM-7351-CAP-0603]  132.72 126.19 180 bottom
C274  4.7uF  [SM-7351-CAP-0603]  143.26 120.6 0 bottom
C275  4.7uF  [SM-7351-CAP-0603]  143.26 118.83 0 bottom
C276  47uF, 10V  [SM-7351-CAP-1206]  151.13 132.8 0 bottom
C277  47uF, 10V  [SM-7351-CAP-1206]  151.13 128.35 0 bottom
C278  47uF, 10V  [SM-7351-CAP-1206]  154.18 118.57 90 top
C279  47uF, 10V  [SM-7351-CAP-1206]  128.52 127.21 90 bottom
C280  47uF, 10V  [SM-7351-CAP-1206]  128.52 121.49 270 bottom
C281  4.7uF  [SM-7351-CAP-0603]  146.3 129.62 90 bottom
C282  4.7uF  [SM-7351-CAP-0603]  149.35 123.27 0 bottom
C283  4.7uF  [SM-7351-CAP-0603]  149.35 125.05 0 bottom
C284  4.7uF  [SM-7351-CAP-0603]  133.22 128.99 180 bottom
C285  4.7uF  [SM-7351-CAP-0603]  140.72 117.43 270 bottom
C286  1uF  [SM-7351-CAP-0402]  110.74 92.66 90 bottom
C287  1uF  [SM-7351-CAP-0402]  108.58 92.66 90 bottom
C288  1uF  [SM-7351-CAP-0402]  109.04 80.04 0 bottom
C289  1uF  [SM-7351-CAP-0402]  115.57 73.23 0 bottom
C290  1uF  [SM-7351-CAP-0402]  106.43 92.66 90 bottom
C291  1uF  [SM-7351-CAP-0402]  108.25 79 0 bottom
C292  1uF  [SM-7351-CAP-0402]  118.24 76.54 270 bottom
C293  1uF  [SM-7351-CAP-0402]  104.39 92.66 90 bottom
C296  1uF  [SM-7351-CAP-0402]  101.73 67.9 270 bottom
C297  1uF  [SM-7351-CAP-0402]  94.11 82.73 180 bottom
C298  1uF  [SM-7351-CAP-0402]  91.34 82.76 180 bottom
C301  2.2uF  [SM-7351-CAP-0402]  141.48 135.97 90 top
C302  2.2uF  [SM-7351-CAP-0402]  139.7 130.38 90 bottom
C303  0.1uF  [SM-7351-CAP-0402]  30.23 24.38 270 top
C304  0.1uF  [SM-7351-CAP-0402]  31.5 39.12 90 top
C305  10uF  [SM-7351-CAP-0805]  45.59 47.71 270 bottom
C306  10uF  [SM-7351-CAP-0805]  45.72 52.91 180 bottom
C307  10uF  [SM-7351-CAP-0805]  49.91 47.71 270 bottom
C308  0.01uF  [SM-7351-CAP-0402]  48.51 52.41 180 top
C309  0.01uF  [SM-7351-CAP-0402]  51.56 48.47 270 bottom
C310  0.01uF  [SM-7351-CAP-0402]  55.63 48.47 270 bottom
C311  150uF  [SM-7351-CAP-2917]  43.05 5.64 180 bottom
C313  0.1uF  [SM-7351-CAP-0402]  122.68 20.45 270 bottom
C314  0.1uF  [SM-7351-CAP-0402]  128.52 26.92 0 bottom
C315  0.01uF  [SM-7351-CAP-0402]  77.22 114.89 90 bottom
C316  1uF  [SM-7351-CAP-0603]  139.95 13.21 180 top
C317  10uF  [SM-7351-CAP-0805]  148.08 120.86 0 bottom
C318  2.2uF  [SM-7351-CAP-0402]  140.46 132.92 0 bottom
C319  0.01uF  [SM-7351-CAP-0402]  187.22 96.73 180 bottom
C320  10uF  [SM-7351-CAP-0805]  55.63 58.37 90 bottom
C321  0.01uF  [SM-7351-CAP-0402]  56.26 52.96 270 top
C322  0.01uF  [SM-7351-CAP-0402]  58.42 55.71 0 bottom
C323  4.7uF  [SM-7351-CAP-0805]  113.79 4.57 90 top
C324  0.01uF  [SM-7351-CAP-0402]  58.42 56.72 0 bottom
C325  4.7uF  [SM-7351-CAP-0805]  103.5 9.02 0 bottom
C326  0.01uF  [SM-7351-CAP-0402]  42.67 56.47 90 bottom
C327  0.01uF  [SM-7351-CAP-0402]  98.17 86.8 90 bottom
C328  0.1uF  [SM-7351-CAP-0402]  90.88 89.54 90 bottom
C329  0.022uF  [SM-7351-CAP-0402]  98.27 81.21 270 bottom
C330  1uF  [SM-7351-CAP-0402]  89.84 89.51 90 bottom
C331  0.047uF  [SM-7351-CAP-0402]  96.62 86.29 180 bottom
C332  0.1uF  [SM-7351-CAP-0402]  109.32 77.98 0 bottom
C333  10uF  [SM-7351-CAP-0805]  98.42 96.09 90 bottom
C334  0.022uF  [SM-7351-CAP-0402]  101.6 78.82 270 bottom
C335  0.01uF  [SM-7351-CAP-0402]  104.65 77.45 270 bottom
C336  0.047uF  [SM-7351-CAP-0402]  102.62 78.82 270 bottom
C337  0.047uF  [SM-7351-CAP-0402]  105.77 77.5 270 bottom
C338  0.022uF  [SM-7351-CAP-0402]  105.92 80.78 0 bottom
C339  0.01uF  [SM-7351-CAP-0402]  101.02 76.97 0 bottom
C340  10uF  [SM-7351-CAP-0805]  114.81 77.42 0 bottom
C341  0.01uF  [SM-7351-CAP-0402]  102.41 85.53 90 bottom
C342  0.022uF  [SM-7351-CAP-0402]  109.93 83.6 0 bottom
C343  0.047uF  [SM-7351-CAP-0402]  102.41 83.42 270 bottom
C344  0.047uF  [SM-7351-CAP-0402]  100.36 81.34 90 bottom
C345  0.022uF  [SM-7351-CAP-0402]  99.31 81.34 90 bottom
C346  0.047uF  [SM-7351-CAP-0402]  106.81 83.06 0 bottom
C347  10uF  [SM-7351-CAP-0805]  111.2 88.24 0 bottom
C348  1uF  [SM-7351-CAP-0402]  110.87 89.79 0 bottom
C349  0.01uF  [SM-7351-CAP-0402]  107.44 84.12 0 bottom
C350  1uF  [SM-7351-CAP-0402]  96.9 129.24 180 top
C351  0.1uF  [SM-7351-CAP-0402]  107.82 85.34 0 bottom
C352  0.1uF  [SM-7351-CAP-0402]  109.32 76.97 0 bottom
C353  0.022uF  [SM-7351-CAP-0402]  104.47 88.77 90 bottom
C354  10uF  [SM-7351-CAP-0805]  116.2 99.78 90 bottom
C355  0.047uF  [SM-7351-CAP-0402]  104.01 86.16 180 bottom
C356  0.01uF  [SM-7351-CAP-0402]  104.01 87.2 180 bottom
C357  1uF  [SM-7351-CAP-0402]  106.55 88.77 90 bottom
C358  0.1uF  [SM-7351-CAP-0402]  105.51 88.77 90 bottom
C360  0.01uF  [SM-7351-CAP-0402]  112.32 79.45 0 bottom
C361  10uF  [SM-7351-CAP-0805]  84.33 93.55 180 bottom
C362  1uF  [SM-7351-CAP-0402]  112.65 74.04 90 bottom
C363  0.1uF  [SM-7351-CAP-0402]  101.24 86.82 90 bottom
C364  1uF  [SM-7351-CAP-0402]  92.02 89.53 270 bottom
C365  0.1uF  [SM-7351-CAP-0402]  108.23 90.5 180 bottom
C367  0.1uF  [SM-7351-CAP-0402]  108.46 88.7 90 bottom
C368  0.1uF  [SM-7351-CAP-0402]  103.94 74.83 270 bottom
C369  1uF  [SM-7351-CAP-0402]  117.47 79.08 0 bottom
C370  1uF  [SM-7351-CAP-0402]  117.47 80.09 0 bottom
C371  0.01uF  [SM-7351-CAP-0402]  107.04 76.79 270 bottom
C372  0.1uF  [SM-7351-CAP-0402]  99.21 74.6 0 bottom
C373  1uF  [SM-7351-CAP-0402]  101.35 89.24 90 bottom
C374  0.01uF  [SM-7351-CAP-0402]  99.31 76.5 270 bottom
C375  10uF  [SM-7351-CAP-0805]  94.64 77.11 180 bottom
C376  0.01uF  [SM-7351-CAP-0402]  102.87 74.83 270 bottom
C377  0.1uF  [SM-7351-CAP-0402]  98.25 76.5 270 bottom
C378  1uF  [SM-7351-CAP-0402]  97.18 76.5 270 bottom
C379  0.1uF  [SM-7351-CAP-0402]  102.36 89.24 90 bottom
C380  0.01uF  [SM-7351-CAP-0402]  101.37 83.7 90 bottom
C381  0.01uF  [SM-7351-CAP-0402]  100.58 78.82 270 bottom
C382  2.2uF  [SM-7351-CAP-0402]  136.91 130.64 180 bottom
C383  2.2uF  [SM-7351-CAP-0402]  137.01 129.39 180 bottom
C384  10uF  [SM-7351-CAP-0805]  120.78 86.19 0 bottom
C385  0.1uF  [SM-7351-CAP-0402]  111.38 75.87 0 bottom
C386  0.01uF  [SM-7351-CAP-0402]  102.49 91.31 180 bottom
C387  10uF  [SM-7351-CAP-0805]  99.59 89.97 90 bottom
C388  0.01uF  [SM-7351-CAP-0402]  103.66 81.34 270 bottom
C389  0.01uF  [SM-7351-CAP-0402]  102.41 81.34 90 bottom
C390  0.01uF  [SM-7351-CAP-0402]  94.36 85.04 90 bottom
C391  0.01uF  [SM-7351-CAP-0402]  93.22 85.04 90 bottom
C392  2.2uF  [SM-7351-CAP-0402]  142.75 124.03 180 bottom
C393  0.01uF  [SM-7351-CAP-0402]  91.31 81.53 180 bottom
C394  0.01uF  [SM-7351-CAP-0402]  96.75 81.67 180 bottom
C395  10uF  [SM-7351-CAP-0805]  104.14 97.36 90 bottom
C396  10uF  [SM-7351-CAP-0805]  86.49 89.62 90 bottom
C399  2.2uF  [SM-7351-CAP-0402]  141.22 131.02 180 bottom
C400  0.01uF  [SM-7351-CAP-0402]  96.22 84.92 180 bottom
C401  0.01uF  [SM-7351-CAP-0402]  97.71 83.43 0 bottom
C402  2.2uF  [SM-7351-CAP-0402]  137.67 133.43 90 bottom
C403  0.01uF  [SM-7351-CAP-0402]  88.49 82.78 180 bottom
C404  0.01uF  [SM-7351-CAP-0402]  91.29 84.13 180 bottom
C405  0.01uF  [SM-7351-CAP-0402]  103.38 89.24 90 bottom
C406  0.01uF  [SM-7351-CAP-0402]  96.93 89.13 90 bottom
C407  1uF  [SM-7351-CAP-0402]  148.34 101.05 180 top
C408  0.01uF  [SM-7351-CAP-0402]  151.38 96.47 0 top
C409  0.01uF  [SM-7351-CAP-0402]  151.38 97.49 0 top
C410  0.01uF  [SM-7351-CAP-0402]  153.16 93.17 90 top
C411  100uF  [SM-7351-CAP-SMDCAN]  182.52 126.57 270 bottom
C412  100uF  [SM-7351-CAP-SMDCAN]  182.52 126.57 270 top
C413  10uF  [SM-7351-CAP-0805]  111.2 86.33 0 bottom
C414  10uF  [SM-7351-CAP-0805]  115.7 86.31 0 bottom
C415  0.1uF  [SM-7351-CAP-0402]  153.09 106.14 270 bottom
C416  4.7uF  [SM-7351-CAP-0603]  151.82 106.14 270 bottom
C417  0.1uF  [SM-7351-CAP-0402]  156.01 103.47 270 bottom
C418  22uF  [SM-7351-CAP-0805]  160.6 107.87 90 bottom
C419  22uF  [SM-7351-CAP-0805]  160.6 107.87 90 top
C420  0.01uF  [SM-7351-CAP-0402]  172.97 75.65 90 top
C421  1uF  [SM-7351-CAP-0603]  187.58 81.66 0 bottom
C424  0.01uF  [SM-7351-CAP-0402]  155.7 98.13 270 top
C425  0.01uF  [SM-7351-CAP-0402]  171.58 72.26 180 top
C426  0.01uF  [SM-7351-CAP-0402]  174.12 89.28 90 bottom
C427  0.01uF  [SM-7351-CAP-0402]  61.21 22.86 180 top
C428  0.01uF  [SM-7351-CAP-0402]  68.71 13.21 0 top
C429  0.01uF  [SM-7351-CAP-0402]  59.26 15.47 180 top
C430  0.01uF  [SM-7351-CAP-0402]  97.79 6.1 180 top
C431  0.1uF  [SM-7351-CAP-0402]  115.44 4.19 90 top
C432  0.1uF  [SM-7351-CAP-0402]  129.67 7.11 270 top
C433  10uF  [SM-7351-CAP-0805]  115.95 8 90 bottom
C434  0.1uF  [SM-7351-CAP-0402]  102.23 12.83 90 bottom
C435  10uF  [SM-7351-CAP-1206]  133.1 8 90 top
C436  0.1uF  [SM-7351-CAP-0402]  45.47 40.26 270 top
C437  0.1uF  [SM-7351-CAP-0402]  44.45 40.26 270 top
C438  0.1uF  [SM-7351-CAP-0402]  74.68 76.66 0 top
C439  0.1uF  [SM-7351-CAP-0402]  74.68 77.68 0 top
C441  100uF  [SM-7351-CAP-SMDCAN]  70.1 65.49 90 bottom
C442  1uF  [SM-7351-CAP-0402]  103.63 78.82 270 bottom
C443  0.01uF  [SM-7351-CAP-0402]  171.32 89.28 90 bottom
C444  0.01uF  [SM-7351-CAP-0402]  169.52 60.28 270 bottom
C445  1uF  [SM-7351-CAP-0402]  101.37 81.34 90 bottom
C446  1uF  [SM-7351-CAP-0402]  90.55 86.11 90 bottom
C447  1uF  [SM-7351-CAP-0402]  94.11 81.66 180 bottom
C448  0.01uF  [SM-7351-CAP-0402]  168.66 63.84 90 bottom
C449  0.1uF  [SM-7351-CAP-0402]  175.26 4.02 270 bottom
C450  10uF  [SM-7351-CAP-0603]  143.13 127.46 270 bottom
C451  0.01uF  [SM-7351-CAP-0402]  141.86 127.46 270 bottom
C452  10uF  [SM-7351-CAP-0603]  139.19 117.43 270 bottom
C453  0.01uF  [SM-7351-CAP-0402]  132.97 127.59 180 bottom
C454  0.1uF  [SM-7351-CAP-0402]  66.93 75.52 90 top
C455  0.1uF  [SM-7351-CAP-0402]  105.28 137.75 0 top
C456  0.1uF  [SM-7351-CAP-0402]  112.65 137.62 0 top
C457  0.1uF  [SM-7351-CAP-0402]  120.78 137.62 0 top
C458  10uF  [SM-7351-CAP-0805]  157.86 126.83 180 bottom
C459  1uF  [SM-7351-CAP-0603]  157.61 126.75 180 top
C460  0.1uF  [SM-7351-CAP-0402]  156.18 120.52 270 top
C461  10uF  [SM-7351-CAP-0805]  162.85 120.69 270 top
C462  10uF  [SM-7351-CAP-0805]  162.85 125.01 90 top
C463  1.1nF  [SM-7351-CAP-0603]  158.24 115.91 0 top
C464  2.2uF  [SM-7351-CAP-0805]  144.53 134.45 90 bottom
C465  2.2uF  [SM-7351-CAP-0805]  142.62 134.45 90 bottom
C466  2.2uF  [SM-7351-CAP-0805]  132.33 133.05 270 bottom
C467  2.2uF  [SM-7351-CAP-0805]  134.49 133.05 270 bottom
C468  2.2uF  [SM-7351-CAP-0805]  136.53 118.95 180 bottom
C469  0.01uF  [SM-7351-CAP-0402]  42.67 38.61 270 top
C470  0.01uF  [SM-7351-CAP-0402]  42.14 44.55 180 top
C471  2.2uF  [SM-7351-CAP-0805]  70.61 108.03 180 bottom
C472  2.2uF  [SM-7351-CAP-0805]  75.44 114.13 90 bottom
C473  47uF  [7343]  74.8 89.41 270 bottom
C474  47uF  [7343]  117.86 89.74 0 bottom
C475  47uF  [7343]  128.02 113.49 90 bottom
C476  2.2uF  [SM-7351-CAP-0402]  158.8 106.27 270 bottom
C477  0.1uF  [SM-7351-CAP-0402]  46.48 24.38 90 top
C478  0.1uF  [SM-7351-CAP-0402]  45.47 24.38 90 top
C479  2.2uF  [SM-7351-CAP-0805]  97.92 131.78 0 top
C480  0.01uF  [SM-7351-CAP-0402]  156.97 95.71 180 top
C481  0.01uF  [SM-7351-CAP-0402]  156.97 94.57 180 top
C482  0.01uF  [SM-7351-CAP-0402]  153.54 98 270 top
C483  10uF  [SM-7351-CAP-0805]  84.33 96.09 180 bottom
C484  1uF  [SM-7351-CAP-0402]  154.43 101.05 0 top
C485  0.01uF  [SM-7351-CAP-0402]  96.14 92.79 0 bottom
C486  0.01uF  [SM-7351-CAP-0402]  96.14 91.78 0 bottom
C487  0.01uF  [SM-7351-CAP-0402]  96.14 90.76 0 bottom
C545  150uF  [SM-7351-CAP-2917]  11.68 44.96 0 top
C546  4.7uF  [SM-7351-CAP-0603]  6.6 38.44 270 bottom
C547  0.01uF  [SM-7351-CAP-0402]  8.76 41.23 0 top
C548  0.01uF  [SM-7351-CAP-0402]  120.27 81.74 0 bottom
C557  0.1uF  [SM-7351-CAP-0402]  33.53 15.37 0 bottom
C558  0.001uF  [SM-7351-CAP-0402]  33.53 14.1 0 bottom
C559  0.1uF  [SM-7351-CAP-0402]  5.46 32.77 180 top
C560  0.001uF  [SM-7351-CAP-0402]  5.46 34.04 180 top
C561  47uF  [SM-7351-CAP-1206]  152.91 137.67 0 top
C562  2.2uF  [SM-7351-CAP-0402]  144.53 122.94 270 bottom
C563  0.01uF  [SM-7351-CAP-0402]  81.91 82.8 180 bottom
C564  0.01uF  [SM-7351-CAP-0402]  99.82 83.44 0 bottom
C565  1uF  [SM-7351-CAP-0402]  81.91 81.41 180 bottom
C566  0.01uF  [SM-7351-CAP-0402]  97.92 78.08 0 bottom
C567  0.01uF  [SM-7351-CAP-0402]  81.28 79.25 180 bottom
C568  1uF  [SM-7351-CAP-0402]  81.28 78.23 180 bottom
C569  1uF  [SM-7351-CAP-0402]  88.65 81.66 180 bottom
C570  0.1uF  [SM-7351-CAP-0402]  91.95 72.77 90 bottom
C571  1uF  [SM-7351-CAP-0402]  85.98 68.2 270 bottom
C572  0.1uF  [SM-7351-CAP-0402]  114.81 75.56 0 bottom
C573  0.1uF  [SM-7351-CAP-0402]  114.81 74.55 0 bottom
C574  0.047uF  [SM-7351-CAP-0402]  109.98 84.71 0 bottom
C575  0.01uF  [SM-7351-CAP-0402]  128.65 46.86 0 top
C576  DNI  [SM-7351-CAP-0402]  161.8 48.89 270 bottom
C577  0.01uF  [SM-7351-CAP-0402]  148.72 73.53 90 top
C578  0.01uF  [SM-7351-CAP-0402]  150.11 73.53 90 top
C579  0.1uF  [SM-7351-CAP-0402]  133.99 84.58 270 bottom
C580  0.1uF  [SM-7351-CAP-0402]  133.99 100.08 270 bottom
C581  0.1uF  [SM-7351-CAP-0402]  51.43 24.38 90 top
C582  0.1uF  [SM-7351-CAP-0402]  50.42 24.38 90 top
C583  DNI  [SM-7351-CAP-0402]  158.24 112.27 0 top
D1  -  [SK1545]  167.16 108.03 90 bottom
D2  -  [SMCJ26CA]  167.67 114.89 90 top
D3  MMSD103T1  [SOD-123]  39.5 112.86 0 bottom
D4  MMSD103T1  [SOD-123]  61.21 112.86 0 bottom
D5  Green LED  [SM_LED_0805]  179.35 37.46 0 top
D6  Green LED  [SM_LED_0805]  179.35 35.31 0 top
D7  Green LED  [SM_LED_0805]  179.35 33.15 0 top
D8  Green LED  [SM_LED_0805]  179.35 30.99 0 top
D9  Green LED  [SM_LED_0805]  179.35 28.83 0 top
D10  Green LED  [SM_LED_0805]  179.35 26.67 0 top
D11  Green LED  [SM_LED_0805]  179.35 24.51 0 top
D12  Green LED  [SM_LED_0805]  179.35 22.35 0 top
D13  Green LED  [SM_LED_0805]  162.74 91.32 180 top
D14  MBR0520LT1  [MBR0520L]  118.62 5.33 90 bottom
D15  MBR0520LT1  [MBR0520L]  118.62 11.18 270 bottom
D16  Red_Green_Blue_LED  [LED-SM1210]  11.94 4.32 270 top
D17  Red_Green_Blue_LED  [LED-SM1210]  16.13 4.32 270 top
D18  Red_Green_Blue_LED  [LED-SM1210]  19.94 4.32 270 top
D19  Red_Green_Blue_LED  [LED-SM1210]  23.88 4.32 270 top
D20  PMEG2010  [DFN1006D-2]  160.91 123.78 90 top
D22  Red_Green_Blue_LED  [LED-SM1210]  72.9 100.16 270 top
D23  Red_Green_Blue_LED  [LED-SM1210]  69.47 100.16 270 top
D24  TLVH431  [SOT23-3-44M]  38.86 93.6 90 bottom
D25  TLVH431  [SOT23-3-44M]  116.97 128.27 180 bottom
F1  Fuse 8A  [FUSE-0154]  167.51 104.6 180 top
FB1  600mAFB10ohm  [HF70ACB201209]  48.26 121.75 180 bottom
FB2  600mAFB10ohm  [HF70ACB201209]  44.2 121.62 180 bottom
FB3  600mAFB10ohm  [HF70ACB201209]  44.2 118.95 180 bottom
FB4  600mAFB10ohm  [HF70ACB201209]  44.2 124.29 180 bottom
FB5  600mAFB10ohm  [HF70ACB201209]  73.02 110.95 180 top
FB6  600mAFB10ohm  [HF70ACB201209]  65.91 121.87 180 top
FB7  600mAFB10ohm  [HF70ACB201209]  66.04 119.08 180 top
FB8  600mAFB10ohm  [HF70ACB201209]  65.91 124.41 180 top
FB9  220OHM2A  [SM-7351-IND-0603]  180.37 16.38 180 top
FB10  220OHM2A  [SM-7351-IND-0603]  163.75 83.32 90 bottom
FB11  220OHM2A  [SM-7351-IND-0603]  163.75 79 270 bottom
FB12  150OHM800mA  [SM-7351-IND-0805]  183.79 20.07 180 bottom
FB13  150OHM800mA  [SM-7351-IND-0805]  47.75 47.71 270 bottom
FB19  150OHM800mA  [SM-7351-IND-0805]  158.5 98.13 180 top
J1  Power Jack RAPC712  [RAPC712]  175.99 111.76 180 top
J2  DNI Connector_Screwdown  [CONN_OSTTC02]  186.47 109.35 90 top
J3  RJ-45 10_100Mb  [CNRJ45-1X1WLED]  17.15 135.26 270 top
J4  HEADER 5  [HEADER_5X1]  43.43 78.36 0 top
J5  RJ-45 10_100Mb  [CNRJ45-1X1WLED]  17.15 111.12 270 top
J6  RJ-45 10_100Mb  [CNRJ45-1X1WLED]  17.15 87 270 top
J7  HEADER 5  [HEADER_5X1]  43.31 70.36 0 top
J8  RJ-45 10_100Mb  [CNRJ45-1X1WLED]  17.15 62.23 270 top
J9  HEADER 12x2  [HDR2X12]  159.03 137.11 90 top
J10  RJ-45 Gigabit  [CNRJ45-1X1WLED-598M]  39.24 132.51 180 top
J12  RJ-45 Gigabit  [CNRJ45-1X1WLED-598M]  60.96 132.51 180 top
J14  Conn_DB9F  [NORCOMP_DB9F_SMD]  94.15 2.14 180 top
J15  SCHA5B0200  [SD-MICRO-SCHA5B0300]  90.89 147.64 180 top
J16  XF2M-3215-1A  [CNXF2M-3215-1A]  82.35 121.65 90 bottom
J17  XF2L-0625-1A  [CNXF2L-0625-1A]  51.87 88.26 90 bottom
J18  CTI JTAG  [HEADER10X2]  182.25 89.41 90 top
J19  USB_MicroAB  [ZX62-AB-5PA]  186.38 14.4 90 top
J21  Header_30x2_Female  [HDR2X30-2MM-177M]  101.35 147.02 0 top
J23  USB2_STD_A  [USB_STD_A_TH]  39.54 13 0 top
J24  HDMIConnA  [SMD_HDMIA_RA]  62.4 3.58 0 top
J37  Header 15x2 Female  [HDR2X15-344M]  184.94 59.05 270 top
J38  HEADER 5  [HEADER_5X1]  152.78 14.22 270 top
J39  HEADER 3  [HEADER_3X1]  158.75 9.14 270 top
J40  HEADER 2  [HEADER_2X1]  69.34 74.25 0 top
J41  HEADER 2  [HEADER_2X1]  106.55 140.04 90 top
J42  HEADER 2  [HEADER_2X1]  114.05 139.91 90 top
J43  HEADER 2  [HEADER_2X1]  122.05 139.91 90 top
J44  DNI HEADER 2  [HEADER_2X1]  83.57 106.89 0 top
J45  USB_MicroAB  [ZX62-AB-5PA]  4.12 41.1 90 bottom
J46  HEADER 4  [HDR1X4-330M]  168.53 11.51 0 top
J49  HEADER 2  [HEADER_2X1]  37.72 20.19 270 top
J50  HEADER 2  [HEADER_2X1]  14.61 40.89 180 top
J51  HEADER 2  [HEADER_2X1]  138.18 63.63 0 top
J52  10061913  [CNPCIE64SMT]  30.39 35.51 0 top
J53  Terminal Block  [CN1792216]  172.21 66.67 90 top
L1  4.7uH  [VLCF5020T]  77.98 143.97 270 top
L2  DA2304-AL  [DA2304]  127.76 8.25 180 bottom
L3  NFM21PC474  [FILT-NFM21PC]  52.83 58.12 270 bottom
L11  ACM2012  [ACM2012H]  43.18 24.13 270 bottom
L12  1uH  [IND_IHLP1616AB]  151 132.67 0 top
L13  1uH  [IND_IHLP1616AB]  151 128.1 0 top
L14  1uH  [IND_IHLP1616AB]  151 123.53 0 top
L15  1uH  [IND_IHLP1616AB]  128.52 127.21 90 top
L16  1uH  [IND_IHLP1616AB]  128.52 121.49 270 top
L17  1uH  [IND_IHLP1616AB]  135.51 114.38 270 top
L18  1uH  [IND_IHLP1616AB]  128.52 132.92 90 top
L19  1uH  [IND_IHLP1616AB]  144.4 114.38 270 top
L20  1uH  [IND_IHLP1616AB]  139.95 114.38 270 top
L21  NFM21PC474  [FILT-NFM21PC]  112.73 82.55 90 bottom
L22  4.7uH  [SMD_SLF7055T]  155.12 111.47 0 bottom
L24  NFM21PC474  [FILT-NFM21PC]  109.09 81.79 180 bottom
L25  NFM21PC474  [FILT-NFM21PC]  88.01 85.93 0 bottom
L26  NFM21PC474  [FILT-NFM21PC]  87.88 79.63 0 bottom
L28  3.3uH  [VLCF5020T]  158.88 131.53 0 top
L29  DLW21SN900HQ2L  [FILT-DLW21S]  55.88 20.32 270 top
L30  DLW21SN900HQ2L  [FILT-DLW21S]  58.42 20.32 270 top
L31  DLW21SN900HQ2L  [FILT-DLW21S]  70.87 20.45 270 top
L32  DLW21SN900HQ2L  [FILT-DLW21S]  73.41 20.45 270 top
L33  ACM2012  [ACM2012H]  9.14 40.98 180 bottom
L34  NFM21PC474  [FILT-NFM21PC]  85.47 83.19 180 bottom
L35  NFM21PC474  [FILT-NFM21PC]  80.14 76.07 0 bottom
NOREF  -  [unnamed]  117.22 96.98 0 top
NOREF#2  -  [unnamed]  87.38 66.88 0 top
NOREF#3  -  [unnamed#2]  5.08 5.08 0 top
NOREF#4  -  [unnamed]  27.94 86.82 0 top
NOREF#5  -  [unnamed]  123.83 22.1 0 top
NOREF#6  -  [unnamed]  62.48 114 0 top
NOREF#7  -  [unnamed]  27.56 61.8 0 top
NOREF#8  -  [#3]  118.75 52.7 0 top
NOREF#9  -  [unnamed]  172.26 88.78 0 top
NOREF#10  -  [unnamed]  29.74 125.66 0 top
NOREF#11  -  [unnamed]  130.56 117.18 0 top
NOREF#12  -  [#3]  0 0 0 top
NOREF#13  -  [#3]  -17.13 -248.13 90 top
NOREF#14  -  [unnamed]  108.97 42.42 0 top
NOREF#15  -  [unnamed]  93.6 22.61 0 top
NOREF#16  -  [unnamed]  156.64 72.39 0 top
NOREF#17  -  [unnamed]  41.1 114.74 0 top
NOREF#18  -  [#3]  190.5 0 90 top
NOREF#19  -  [#3]  -17.13 -99.99 0 top
NOREF#20  -  [#3]  -29.48 8.76 90 top
NOREF#21  -  [unnamed#2]  185.42 147.32 0 top
NOREF#22  -  [unnamed]  51.46 125.66 0 top
NOREF#23  -  [unnamed]  27.69 104.35 0 top
NOREF#24  -  [unnamed]  184.18 8.89 0 top
NOREF#25  -  [unnamed#2]  185.42 5.08 0 top
NOREF#26  -  [unnamed]  148.59 135.97 0 top
NOREF#27  -  [#3]  -29.48 156.9 0 top
NOREF#28  -  [unnamed#2]  5.08 147.32 0 top
NOREF#29  -  [unnamed]  5.08 10.79 0 top
NOREF#30  -  [unnamed]  181.25 143.85 0 top
NOREF#31  -  [unnamed]  36.96 51.26 0 top
NOREF#32  -  [unnamed]  78.74 41.78 0 top
NOREF#33  -  [unnamed]  4.45 142.96 0 top
NOREF#34  -  [unnamed]  36.2 75.65 0 top
NOREF#35  -  [#3]  -15.14 -195.3 0 top
NOREF#36  -  [unnamed]  57.78 49.48 270 bottom
NOREF#37  -  [unnamed]  4.45 142.96 180 bottom
NOREF#38  -  [unnamed]  104.77 135.21 180 bottom
NOREF#39  -  [unnamed]  5.08 10.79 180 bottom
NOREF#40  -  [unnamed]  160.66 89.49 0 bottom
NOREF#41  -  [unnamed]  188.09 70.95 0 bottom
NOREF#42  -  [unnamed]  147.96 102.32 0 bottom
NOREF#43  -  [unnamed]  26.16 123.02 270 bottom
NOREF#44  -  [unnamed]  184.18 8.89 180 bottom
NOREF#45  -  [unnamed]  181.25 143.85 180 bottom
NOREF#46  -  [unnamed]  50.04 57.36 270 bottom
NOREF#47  -  [unnamed]  86.49 118.06 180 bottom
Q1  BSS138  [SOT23-3]  13.72 3.76 90 bottom
Q2  BSS138  [SOT23-3]  20.32 3.76 90 bottom
Q3  BSS138  [SOT23-3]  13.72 10.37 90 bottom
Q4  BSS138  [SOT23-3]  20.32 10.37 90 bottom
Q5  BSS138  [SOT23-3]  13.72 7.07 90 bottom
Q6  BSS138  [SOT23-3]  20.32 7.07 90 bottom
Q7  FDT434P  [SOT223-4]  45.59 112.6 270 bottom
Q8  FDT434P  [SOT223-4]  67.44 111.84 90 top
Q9  BSS138  [SOT23-3]  74.3 148.54 90 top
Q10  BSS138  [SOT23-3]  13.72 20.53 90 bottom
Q11  BSS138  [SOT23-3]  13.72 13.92 90 bottom
Q12  BSS138  [SOT23-3]  20.32 17.23 90 bottom
Q13  BSS138  [SOT23-3]  20.32 13.92 90 bottom
Q14  BSS138  [SOT23-3]  20.32 20.66 90 bottom
Q15  BSS138  [SOT23-3]  13.72 17.23 90 bottom
Q16  BSS138  [SOT23-3]  143.13 13.84 0 top
Q20  BSS138  [SOT23-3]  79.98 103.22 180 bottom
Q21  BSS138  [SOT23-3]  76.55 103.22 180 bottom
Q22  BSS138  [SOT23-3]  73.12 103.22 180 bottom
Q23  BSS138  [SOT23-3]  69.85 94.06 180 bottom
Q24  BSS138  [SOT23-3]  69.72 86.95 180 bottom
Q25  BSS138  [SOT23-3]  69.34 101.17 180 bottom
Q26  MMBT2907A  [SOT23-3-44M]  38.86 97.16 90 bottom
Q27  MMBT2907A  [SOT23-3-44M]  113.41 128.27 180 bottom
R2  10K  [SM-7351-RES-0402]  127.89 64.85 0 top
R3  22  [SM-7351-RES-0402]  183.9 89.41 270 bottom
R4  1M  [SM-7351-RES-0402]  77.6 82.38 270 top
R5  0  [SM-7351-RES-0402]  79.25 82.89 180 top
R6  0  [SM-7351-RES-0402]  138.68 70.36 180 top
R7  0  [SM-7351-RES-0402]  124.08 65.49 0 top
R8  0  [SM-7351-RES-0402]  124.08 69.3 0 top
R9  0  [SM-7351-RES-0402]  136.91 126.45 180 bottom
R10  10K  [SM-7351-RES-0402]  170.05 45.76 180 bottom
R11  100  [SM-7351-RES-0402]  168.15 53.55 0 bottom
R12  100  [SM-7351-RES-0402]  170.05 42.93 0 bottom
R13  0  [SM-7351-RES-0402]  69.74 82.33 180 top
R14  0  [SM-7351-RES-0402]  130.43 114.76 270 top
R15  0  [SM-7351-RES-0402]  132.72 114.76 270 top
R16  1K  [SM-7351-RES-0402]  134.49 122.38 180 bottom
R17  1K  [SM-7351-RES-0402]  137.13 122.3 180 bottom
R18  10K  [SM-7351-RES-0402]  144.54 126.96 90 bottom
R19  0  [SM-7351-RES-0402]  142.49 140.54 90 top
R20  0  [SM-7351-RES-0402]  142.88 135.97 90 top
R21  1K  [SM-7351-RES-0402]  138.91 128.35 270 bottom
R22  10K  [SM-7351-RES-0402]  89.79 108.79 270 top
R23  0  [SM-7351-RES-0402]  101.85 112.48 270 top
R24  0  [SM-7351-RES-0402]  101.98 99.78 270 top
R25  0  [SM-7351-RES-0402]  98.68 108.79 270 top
R26  0  [SM-7351-RES-0402]  91.06 124.16 90 top
R27  0  [SM-7351-RES-0402]  91.06 108.79 270 top
R28  0  [SM-7351-RES-0402]  101.35 124.16 90 top
R29  0  [SM-7351-RES-0402]  97.41 124.16 90 top
R30  0  [SM-7351-RES-0402]  92.33 124.16 90 top
R31  0  [SM-7351-RES-0402]  101.85 114.51 270 top
R32  10K  [SM-7351-RES-0402]  124.71 40.51 0 top
R33  10K  [SM-7351-RES-0402]  108.84 40.51 180 top
R34  10K  [SM-7351-RES-0402]  124.71 38.48 0 top
R35  10K  [SM-7351-RES-0402]  108.84 39.5 180 top
R36  18.2K  [SM-7351-RES-0402]  124.59 42.75 180 top
R37  10K  [SM-7351-RES-0402]  124.71 39.5 0 top
R38  10K  [SM-7351-RES-0402]  108.84 37.46 180 top
R39  10K  [SM-7351-RES-0402]  124.71 37.46 0 top
R40  10K  [SM-7351-RES-0402]  108.84 38.48 180 top
R41  240  [SM-7351-RES-0402]  93.6 30.1 180 top
R42  240  [SM-7351-RES-0402]  124.08 30.1 180 top
R44  240  [SM-7351-RES-0402]  108.84 30.1 180 top
R45  10K  [SM-7351-RES-0402]  111.12 15.11 0 top
R46  49.9  [SM-7351-RES-0402]  127.51 31.5 180 bottom
R47  49.9  [SM-7351-RES-0402]  127.51 30.48 180 bottom
R48  10K  [SM-7351-RES-0402]  111.12 13.97 180 top
R49  47  [SM-7351-RES-0402]  124.08 29.59 180 bottom
R50  47  [SM-7351-RES-0402]  108.84 26.42 0 top
R51  47  [SM-7351-RES-0402]  108.71 30.35 0 bottom
R52  47  [SM-7351-RES-0402]  108.71 27.81 0 bottom
R53  47  [SM-7351-RES-0402]  117.22 21.72 90 bottom
R54  47  [SM-7351-RES-0402]  118.24 21.72 90 bottom
R55  47  [SM-7351-RES-0402]  119.25 21.72 90 bottom
R56  100K  [SM-7351-RES-0402]  108.2 11 270 top
R57  47  [SM-7351-RES-0402]  116.46 21.72 90 top
R58  47  [SM-7351-RES-0402]  114.17 21.72 90 bottom
R59  47  [SM-7351-RES-0402]  124.08 26.29 180 top
R60  47  [SM-7351-RES-0402]  116.2 21.72 90 bottom
R61  47  [SM-7351-RES-0402]  124.08 25.02 180 bottom
R62  47  [SM-7351-RES-0402]  113.16 21.72 90 top
R63  47  [SM-7351-RES-0402]  120.27 21.72 90 top
R64  47  [SM-7351-RES-0402]  114.17 21.72 90 top
R65  47  [SM-7351-RES-0402]  117.47 21.72 90 top
R66  47  [SM-7351-RES-0402]  124.08 31.88 180 top
R67  0  [SM-7351-RES-0402]  106.3 11.51 180 top
R68  47  [SM-7351-RES-0402]  121.54 21.72 90 bottom
R69  10  [SM-7351-RES-0402]  104.65 17.4 180 top
R70  47  [SM-7351-RES-0402]  115.32 21.72 90 top
R71  47  [SM-7351-RES-0402]  118.49 21.72 90 top
R72  47  [SM-7351-RES-0402]  115.19 21.72 90 bottom
R73  47  [SM-7351-RES-0402]  124.08 27.56 180 top
R74  47  [SM-7351-RES-0402]  120.4 21.72 90 bottom
R75  47  [SM-7351-RES-0402]  108.84 27.56 0 top
R76  2.2K  [SM-7351-RES-0402]  25.91 121.11 0 bottom
R77  0  [SM-7351-RES-0402]  22.48 136.48 90 bottom
R78  0  [SM-7351-RES-0402]  7.75 141.69 180 bottom
R79  0  [SM-7351-RES-0402]  144.65 98.17 180 top
R80  0  [SM-7351-RES-0402]  144.65 97.16 180 top
R81  0  [SM-7351-RES-0402]  144.53 91.57 180 top
R82  0  [SM-7351-RES-0402]  144.65 95.12 180 top
R83  0  [SM-7351-RES-0402]  25.15 112.65 270 bottom
R84  0  [SM-7351-RES-0402]  144.53 88.14 180 top
R85  0  [SM-7351-RES-0402]  144.65 99.69 180 top
R86  0  [SM-7351-RES-0402]  24.13 112.65 270 bottom
R87  0  [SM-7351-RES-0402]  23.11 112.65 270 bottom
R88  0  [SM-7351-RES-0402]  21.08 114.17 270 bottom
R89  0  [SM-7351-RES-0402]  7.24 119.72 180 bottom
R90  0  [SM-7351-RES-0402]  19.81 114.17 270 bottom
R91  0  [SM-7351-RES-0402]  18.54 114.17 270 bottom
R92  0  [SM-7351-RES-0402]  17.53 115.82 270 bottom
R93  0  [SM-7351-RES-0402]  6.48 132.03 270 bottom
R94  0  [SM-7351-RES-0402]  26.92 108.84 270 bottom
R95  0  [SM-7351-RES-0402]  22.86 110.62 270 bottom
R96  0  [SM-7351-RES-0402]  25.91 118.83 0 bottom
